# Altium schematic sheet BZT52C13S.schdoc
size 127 x 101 mm
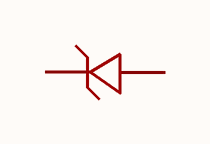
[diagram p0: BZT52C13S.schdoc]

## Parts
ZD?  bzt52c13s_c22616  [SOD-323_L1.8-W1.3-LS2.5-RD]  (value not drawn)

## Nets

Not connected (* = marked no-connect by the designer): ZD? 1(K) 2(A)

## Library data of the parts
ZD? = bzt52c13s_c22616: 二极管配置:1个独立式;稳压值(标称值):13V;稳压值(范围值):12.4V~14.1V;耗散功率(Pd):200mW;; Manufacturer: CJ(江苏长电/长晶); AddInBom: yes; ModelId: db63db13d9e342eb939127d413d6200b; ModelTransform: 104.3305,51.181,0,0,0,0,0,-0.004,0; Diode Configuration: 1个独立式; Zener Voltage(Nom): 13V; Reverse Leakage Current (Ir): 100nA@8V; Pd - Power Dissipation: 200mW; Impedance(Zzt): 30Ω; Impedance(Zzk): 170Ω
